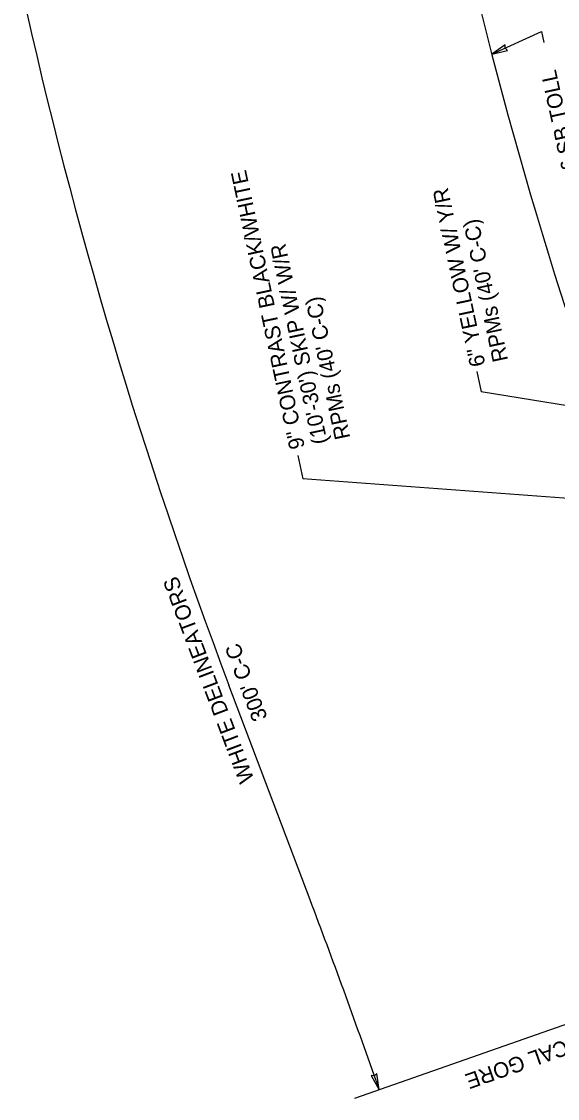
# Model space of a CAD drawing. Extents: x 578088 to 579220, y 1508751 to 1510400.
# Drawn here: x 578106.3 to 578348.8, y 1509420.7 to 1509907.9 of the extents above; entities that cross this region are included whole.
import ezdxf

# ---------------------------------------------------------------- set-up
doc = ezdxf.new("R2010")
doc.units = 0
for name, color, linetype in [('18', 7, 'Continuous'), ('41', 7, 'Continuous'), ('52', 7, 'Continuous')]:
    doc.layers.add(name, color=color, linetype=linetype)

msp = doc.modelspace()

# ---------------------------------------------------------------- linework, layer by layer
at = {"layer": '41'}
msp.add_arc((580335.96, 1510415.53), 2083.48, 192.46859, 200.71859, dxfattribs=at)
at = {"layer": '52'}
for p, q in [((578319.05, 1509893.05), (578341.51, 1509903.42)), ((578341.51, 1509903.42), (578342.57, 1509898.4)), ((578325.07, 1509897.32), (578319.05, 1509893.05)), ((578325.13, 1509895.86), (578325.07, 1509897.32)), ((578319.05, 1509893.05), (578326.22, 1509894.82)), ((578326.22, 1509894.82), (578325.13, 1509895.86)), ((578312.28, 1509749.51), (578314.24, 1509740.29)), ((578420.78, 1509723.2), (578314.24, 1509740.29)), ((578231.31, 1509711.57), (578233.54, 1509701.06)), ((578413.27, 1509687.7), (578233.54, 1509701.06)), ((578236.91, 1509510.5), (578200.15, 1509607.69)), ((578456.88, 1509490.85), (578256.98, 1509420.69)), ((578265.94, 1509430.93), (578264.49, 1509431.01)), ((578264.49, 1509431.01), (578268.17, 1509424.61)), ((578267.08, 1509431.92), (578265.94, 1509430.93)), ((578268.17, 1509424.61), (578267.08, 1509431.92)), ((578266.74, 1509428.68), (578268.17, 1509424.61))]:
    msp.add_line(p, q, dxfattribs=at)
for centre, radius, start, end in [((580335.96, 1510415.53), 2283.48, 192.46859, 200.71859), ((574851.28, 1508229.92), 3619.72, 19.34015, 20.71859)]:
    msp.add_arc(centre, radius, start, end, dxfattribs=at)

# ---------------------------------------------------------------- texts
at = {"layer": '18'}
for s, p in [('WHITE DELINEATORS', (578211.69, 1509564.95)), ("300' C-C", (578217.7, 1509592.96))]:
    msp.add_text(s, height=7, rotation=110.7186, dxfattribs=at).set_placement(p)
at = {"layer": '52'}
for s, rotation, p in [('£ SB TOLL', 102.25, (578357.83, 1509841.2)), ('9" CONTRAST BLACK/WHITE', 102, (578234.56, 1509715.22)), ('6" YELLOW W/ Y/R', 102, (578316.23, 1509752.51)), ("RPMs (40' C-C)", 102, (578326.5, 1509754.69)), ("(10'-30') SKIP W/ W/R", 102, (578244.83, 1509717.41)), ("RPMs (40' C-C)", 102, (578255.1, 1509719.59)), ('PHYSICAL GORE', 199.3587, (578378.61, 1509456.73))]:
    msp.add_text(s, height=7, rotation=rotation, dxfattribs=at).set_placement(p)

doc.saveas('drawing.dxf')
